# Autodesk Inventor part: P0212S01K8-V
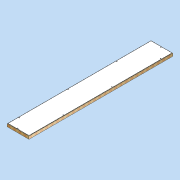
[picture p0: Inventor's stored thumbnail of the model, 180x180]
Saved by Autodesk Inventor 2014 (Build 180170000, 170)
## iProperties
Created: 2011-09
Part Number: P0212S01K8-V
Document SubType Name: Modeling
Designer: david.appleford
Density: 0.206786 g/cm^3
Description: 0.5w x 3w 01 Panel - 8 Locks
Mass: 32000 g
Surface Area: 45569.4 cm^2
Volume: 154749 cm^3
Cost Center: £134.00
Material: Generic
Appearance: Wood (Pine)
Justset: False
Title: 0.5w x 3w 01 Panel 8 Locks
Author: david.appleford
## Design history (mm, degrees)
sketch "Sketch1"
  geometry: L1 (0, 0)-(610, 0); L2 (610, 0)-(610, 3660); L3 (610, 3660)-(0, 3660); L4 (0, 3660)-(0, 0); L5 (34, 3626)-(576, 3626); L6 (576, 3626)-(576, 34); L7 (576, 34)-(34, 34); L8 (34, 34)-(34, 3626)
  constraints: 16 end point, 4 parallel, 2 perpendicular, 1 horizontal, 3 other
  dimensions: "d0" = 610 distance between parallel lines of L2 L4 (= 0.5 x w); "d1" = 3660 distance between parallel lines of L1 L3 (= 3 x w); "d2" = 34 distance between parallel lines of L5 L3 (= 0.5 x t)
extrude "Extrusion1" new body sketch "Sketch1" distance "d3" = 68 (= t); taper "d4" = 0 deg
sketch "Sketch2"
  geometry: L1 (576, 3626)-(576, 34) reference; L2 (34, 3626)-(576, 3626) reference; L3 (34, 34)-(34, 3626) reference; L4 (576, 34)-(34, 34) reference; L5 (566, 3616)-(566, 44); L6 (566, 44)-(44, 44); L7 (44, 44)-(44, 3616); L8 (44, 3616)-(566, 3616); 1 further point
  constraints: 8 end point, 3 other
  dimensions: "d5" = 10 distance between parallel lines of L8 L2
extrude "Extrusion2" join sketch "Sketch2" distance "d6" = 6; taper "d7" = 0 deg
sketch "Sketch3"
  geometry: L1 (-44, 3616)-(-566, 3616) reference; L2 (-566, 3616)-(-566, 44) reference; L3 (-44, 44)-(-44, 3616) reference; L4 (-566, 44)-(-44, 44) reference; 1 further point
extrude "Extrusion3" join sketch "Sketch3" distance "d8" = 6 (= sw); taper "d9" = 0 deg
sketch "Sketch4"
  geometry: L1 (34, 3626)-(576, 3626) reference; L2 (576, 3626)-(576, 34) reference; L3 (576, 34)-(34, 34) reference; L4 (34, 34)-(34, 3626) reference; 9 further points
  constraints: 4 vertical alignment
  dimensions: "d10" = 28 distance from line of point (305, 3598) L1 (= k); "d11" = 28 distance from line of L2 point (548, 3355) (= k); "d13" = 28 distance from line of point (62, 305) L4 (= k); "d14" = 305 horizontal distance of point (305, 3598) point (0, 0) (= 0.25 x w); "d16" = 305 vertical distance of point (62, 305) point (0, 0) (= 0.25 x w); "d17" = 1220 distance of point (62, 305) point (62, 1525) (= w); "d18" = 1220 distance of point (62, 2745) point (62, 1525) (= w); "d19" = 610 vertical distance of point (548, 915) point (62, 305) (= 0.5 x w); "d20" = 1220 distance of point (548, 915) point (548, 2135) (= w); "d21" = 1220 distance of point (548, 3355) point (548, 2135) (= w); "d29" = 28 distance from line of point (271, 62) L3 (= k); "d30" = 305 distance from line of point (271, 62) L2 (= 0.25 x w)
hole "Hole1" sketch "Sketch4" at (305, 3598), (62, 2745), (62, 1525), (62, 305), (548, 3355), (548, 2135), (548, 915), (271, 62) diameter "d22" = 16.3; stored, may be unused: countersink angle "d26" = 90 deg, drill point angle "d28" = 118 deg; dims "d23" = 6, "d24" = 4, "d25" = 2, "d27" = 6
body "Solid1"
node "Projected Loop1"
other parameters: "w" = 1220 [user parameter; used in 10 equation terms], "t" = 68 [user parameter; used in 2 equation terms], "e" = 16 [user parameter], "sw" = 6 [user parameter; used in 1 equation term], "sc" = 9 [user parameter], "sf" = 12 [user parameter], "k" = 28 [user parameter; used in 4 equation terms], "hd" = 12 [user parameter]
